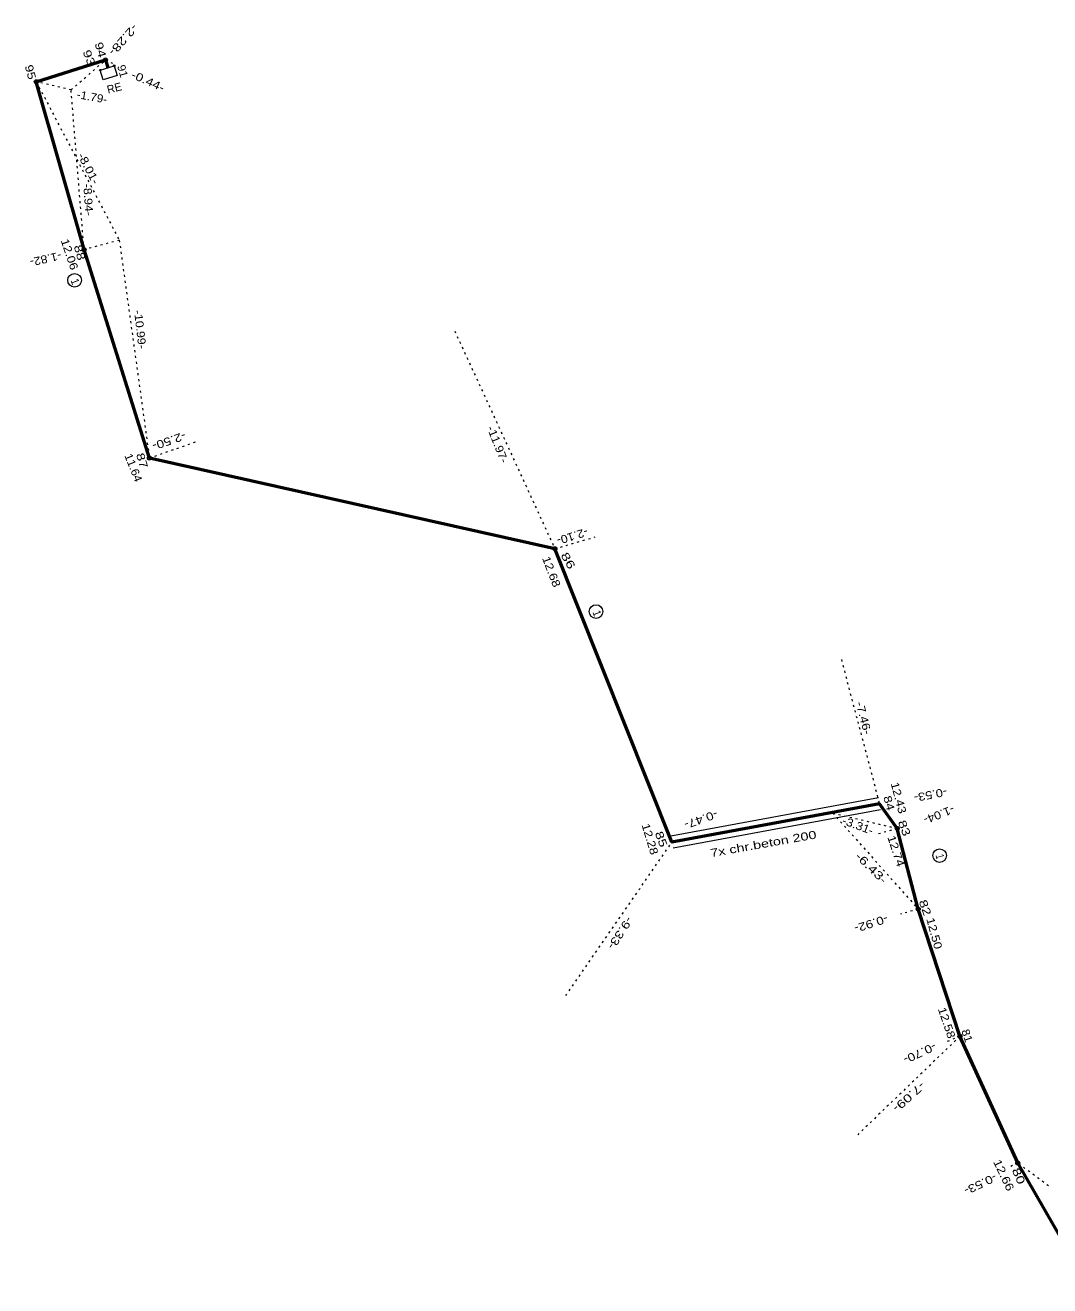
# Model space of a CAD drawing. Extents: x -603113 to -602961, y -1157278 to -1156712.
# Drawn here: x -603112.6 to -603061.3, y -1156775.3 to -1156712.3 of the extents above; entities that cross this region are included whole.
import ezdxf
from ezdxf.enums import TextEntityAlignment as Align

# ---------------------------------------------------------------- set-up
doc = ezdxf.new("R2010")
doc.units = 0
doc.header["$LTSCALE"] = 0.16
doc.header["$PDMODE"] = 32
doc.header["$PDSIZE"] = 0.08
doc.linetypes.add('DOTTED', pattern=[1.5, 0.3, -1.2])
for name, color, linetype, lineweight in [('12', 7, 'Continuous', 53), ('14', 7, 'DOTTED', 13), ('15', 7, 'Continuous', 13), ('17', 7, 'Continuous', 13), ('5', 7, 'Continuous', 13)]:
    doc.layers.add(name, color=color, linetype=linetype, lineweight=lineweight)
doc.layers.add('35', color=7, linetype='Continuous')

msp = doc.modelspace()

# ---------------------------------------------------------------- linework, layer by layer
at = {"layer": '12'}
msp.add_line((-603108.54, -1156714.01), (-603108.417, -1156714.399), dxfattribs=at)
for points in [[(-603080.22, -1156753.11), (-603086.075, -1156738.438), (-603106.344, -1156733.906), (-603109.611, -1156723.489), (-603112, -1156715.1), (-603108.54, -1156714.01)], [(-603059.389, -1156775.282), (-603062.935, -1156769.141), (-603065.821, -1156762.81), (-603067.909, -1156756.453), (-603068.959, -1156752.425), (-603069.846, -1156751.19), (-603080.22, -1156753.11)]]:
    msp.add_lwpolyline(points, dxfattribs=at)
at = {"layer": '14'}
for p, q in [((-603091.08, -1156727.56), (-603086.075, -1156738.438)), ((-603086.075, -1156738.438), (-603084.06, -1156737.853)), ((-603072.18, -1156751.65), (-603068.959, -1156752.425)), ((-603072.18, -1156751.65), (-603067.909, -1156756.453)), ((-603068.959, -1156752.425), (-603069.955, -1156752.715)), ((-603067.909, -1156756.453), (-603068.792, -1156756.71)), ((-603065.821, -1156762.81), (-603070.93, -1156767.73)), ((-603065.821, -1156762.81), (-603066.463, -1156763.08)), ((-603062.935, -1156769.141), (-603063.407, -1156769.387)), ((-603061.4, -1156770.29), (-603062.935, -1156769.141))]:
    msp.add_line(p, q, dxfattribs=at)
for points in [[(-603110.26, -1156715.51), (-603108.54, -1156714.01), (-603108.14, -1156714.19)], [(-603107.85, -1156723.02), (-603106.344, -1156733.906), (-603103.98, -1156733.08)], [(-603071.75, -1156743.98), (-603069.846, -1156751.19), (-603070.356, -1156751.338)], [(-603085.53, -1156760.78), (-603080.22, -1156753.11), (-603079.765, -1156752.979)]]:
    msp.add_lwpolyline(points, dxfattribs=at)
msp.add_lwpolyline([(-603107.85, -1156723.02), (-603109.611, -1156723.489), (-603110.26, -1156715.51), (-603112, -1156715.1)], close=True, dxfattribs=at)
at = {"layer": '15'}
for centre, radius in [((-603108.54, -1156714.01), 0.1), ((-603112, -1156715.1), 0.1), ((-603109.611, -1156723.489), 0.1), ((-603110.087, -1156725.0244), 0.3414), ((-603106.344, -1156733.906), 0.1), ((-603086.075, -1156738.438), 0.1), ((-603084.015, -1156741.5834), 0.3414), ((-603068.959, -1156752.425), 0.1), ((-603066.8364, -1156753.7811), 0.3414), ((-603067.909, -1156756.453), 0.1), ((-603065.821, -1156762.81), 0.1), ((-603062.935, -1156769.141), 0.1)]:
    msp.add_circle(centre, radius, dxfattribs=at)
for p in [(-603108.54, -1156714.01), (-603108.105, -1156714.3), (-603112, -1156715.1), (-603108.8, -1156714.52), (-603109.611, -1156723.489), (-603106.344, -1156733.906), (-603086.075, -1156738.438), (-603069.846, -1156751.19), (-603068.959, -1156752.425), (-603080.22, -1156753.11), (-603067.909, -1156756.453), (-603065.821, -1156762.81), (-603062.935, -1156769.141)]:
    msp.add_point(p, dxfattribs=at)
at = {"layer": '17'}
for p, q in [((-603069.9, -1156750.895), (-603080.274, -1156752.815)), ((-603069.791, -1156751.484), (-603080.165, -1156753.404))]:
    msp.add_line(p, q, dxfattribs=at)
at = {"layer": '5'}
msp.add_lwpolyline([(-603108.8, -1156714.52), (-603108.105, -1156714.3), (-603107.953, -1156714.781), (-603108.648, -1156715.001)], close=True, dxfattribs=at)

# ---------------------------------------------------------------- texts
at = {"layer": '14'}
for s, rotation, width, p in [('-2.28-', 228.742, 1.35, (-603107.172, -1156712.162)), ('-0.44-', 335.63, 1.25, (-603107.292, -1156714.887)), ('-1.79-', 349.718, 1.1, (-603110.005, -1156715.914)), ('-8.01-', 297.417, 1.2, (-603109.946, -1156718.777)), ('-8.94-', 273.714, 1.15, (-603109.649, -1156720.212)), ('-1.82-', 192.6, 1.15, (-603110.787, -1156723.589)), ('-10.99-', 276.59, 1.15, (-603107.114, -1156726.532)), ('-2.50-', 199.016, 1.25, (-603104.597, -1156732.58)), ('-11.97-', 291.756, 1.15, (-603089.48, -1156732.391)), ('-2.10-', 197.504, 1.15, (-603084.489, -1156737.39)), ('-7.46-', 284.47, 1.2, (-603071.032, -1156746.137)), ('-0.53-', 191.139, 1.2, (-603066.508, -1156750.386)), ('-0.47-', 199.77, 1.25, (-603078.013, -1156751.493)), ('-1.04-', 201.758, 1.15, (-603066.191, -1156751.251)), ('-3.31-', 339.757, 1.15, (-603071.744, -1156752.186)), ('-6.43-', 315.61, 1.4, (-603071.093, -1156753.853)), ('-9.33-', 237.084, 1.3, (-603082.474, -1156756.782)), ('-0.92-', 197.929, 1.25, (-603069.491, -1156756.723)), ('-0.70-', 204.937, 1.25, (-603067.117, -1156763.102)), ('-7.09-', 222.074, 1.4, (-603067.775, -1156765.039)), ('-0.53-', 205.717, 1.25, (-603064.092, -1156769.638))]:
    msp.add_text(s, height=0.4, rotation=rotation, dxfattribs=dict(at, width=width)).set_placement(p)
at = {"layer": '15'}
for s, rotation, width, p in [('94', 285.903, 1.3, (-603109.087, -1156713.183)), ('93', 291.086, 1.35, (-603109.688, -1156713.595)), ('95', 285.005, 1.25, (-603112.579, -1156714.307)), ('91', 285.903, 1.05, (-603107.957, -1156714.319)), ('88', 286.232, 1.3, (-603110.13, -1156723.319)), ('1', 290.636, 0.9, (-603110.291, -1156725.028)), ('87', 287.359, 1.3, (-603107.017, -1156733.726)), ('86', 299.578, 1.45, (-603085.796, -1156738.759)), ('1', 290.636, 0.9, (-603084.199, -1156741.608)), ('84', 285.324, 1.25, (-603069.657, -1156750.847)), ('83', 290.594, 1.35, (-603068.928, -1156752.098)), ('85', 290.457, 1.35, (-603081.082, -1156752.652)), ('1', 283.912, 0.75, (-603067.039, -1156753.761)), ('82', 289.65, 1.35, (-603067.885, -1156756.068)), ('81', 288.798, 1.1, (-603065.757, -1156762.536)), ('80', 293.391, 1.4, (-603063.233, -1156769.492))]:
    msp.add_text(s, height=0.4, rotation=rotation, dxfattribs=dict(at, width=width)).set_placement(p)
msp.add_text('RE', height=0.4, rotation=14.476, dxfattribs=at).set_placement((-603108.408, -1156715.699))
at = {"layer": '17', "width": 1.35}
msp.add_text('7x chr.beton 200', height=0.4, rotation=10.087, dxfattribs=at).set_placement((-603078.264, -1156753.857))
at = {"layer": '35'}
for s, rotation, width, p in [('12.06', 288.702, 1.2, (-603110.5265, -1156723.7894)), ('11.64', 291.861, 1.1, (-603107.3295, -1156734.462)), ('12.68', 290.925, 1.2, (-603086.4321, -1156739.6596)), ('12.43', 284.961, 1.2, (-603069.0814, -1156750.9419)), ('12.28', 286.969, 1.2, (-603081.508, -1156753.0116)), ('12.74', 288.415, 1.2, (-603069.2029, -1156753.6143)), ('12.50', 285.446, 1.2, (-603067.2944, -1156757.7187)), ('12.58', 288.806, 1.2, (-603066.6711, -1156762.201)), ('12.66', 295.383, 1.25, (-603063.8113, -1156769.8363))]:
    msp.add_text(s, height=0.4, rotation=rotation, dxfattribs=dict(at, width=width)).set_placement(p, align=Align.CENTER)

doc.saveas('drawing.dxf')
